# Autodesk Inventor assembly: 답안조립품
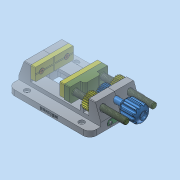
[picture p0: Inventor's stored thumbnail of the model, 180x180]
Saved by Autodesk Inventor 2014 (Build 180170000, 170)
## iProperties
Created: 2021-03
Part Number: 답안조립품
Document SubType Name: Assembly
Designer: NET
Mass: 1539.7 g
Surface Area: 974.155 cm^2
Volume: 352.602 cm^3
Density: 4.36669 g/cm^3
Author: NET
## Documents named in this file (10)
- C:\Users\NET\Desktop\610306V1017\답안조립품.iam
- C:\Users\NET\Desktop\610306V1017\바이스본체 A.ipt
- C:\Users\NET\Desktop\610306V1017\바이스본체 B.ipt
- C:\Users\NET\Desktop\610306V1017\고정 플레이트.ipt
- C:\Users\NET\Desktop\610306V1017\지지대.ipt
- C:\Users\NET\Desktop\610306V1017\스퍼기어.ipt
- C:\Users\NET\Desktop\610306V1017\슬라이딩 부품.ipt
- C:\Users\NET\Desktop\610306V1017\핸들.ipt
- C:\Users\NET\Desktop\610306V1017\십자오목머리나사 M3.ipt
- C:\Users\NET\Desktop\610306V1017\십자접시머리나사 M4.ipt
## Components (3 placed, 2 different names)
1. 고정 플레이트:1
2. 고정 플레이트:2
3. 핸들:1 — 각도:1
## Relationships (1: Angle 1)
- 각도:1 [Angle]: 핸들:1
